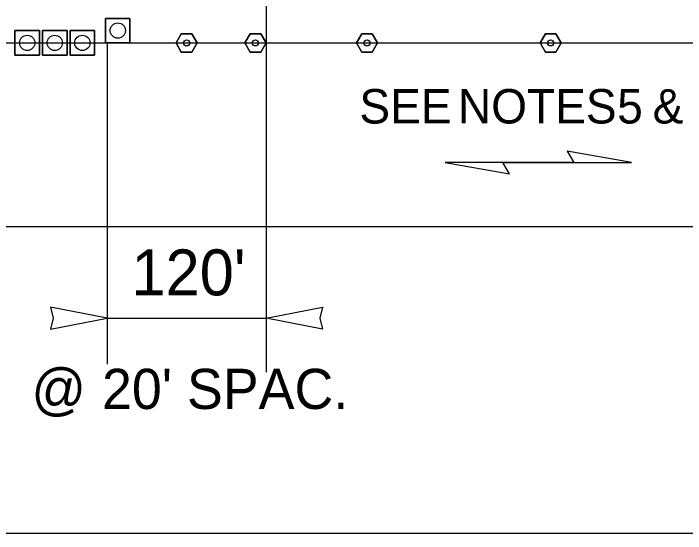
# Model space of a CAD drawing. Extents: x 99999.1 to 100095.7, y 99995 to 100010.7.
# Drawn here: x 100046.407 to 100047.578, y 100008.289 to 100009.196 of the extents above; entities that cross this region are included whole.
import ezdxf

# ---------------------------------------------------------------- set-up
doc = ezdxf.new("R2010")
doc.units = 0
for name, color, linetype in [('RD_ED_ShoulderPavedEdge', 7, 'Continuous'), ('RD_MK_LineEdgeWhite', 7, 'Continuous'), ('SH_TI_Tables', 7, 'Continuous'), ('TR_WZ_TrafficCone', 7, 'Continuous'), ('TR_WZ_TubularMarker', 7, 'Continuous'), ('TR_WZ_WorkZoneDetails', 7, 'Continuous'), ('TR_WZ_WorkZoneTextCurrent', 7, 'Continuous')]:
    doc.layers.add(name, color=color, linetype=linetype)

msp = doc.modelspace()

# ---------------------------------------------------------------- linework, layer by layer
at = {"layer": 'RD_ED_ShoulderPavedEdge'}
msp.add_line((100045.3842, 100008.8243), (100049.3016, 100008.8243), dxfattribs=at)
at = {"layer": 'RD_MK_LineEdgeWhite'}
msp.add_line((100045.3842, 100009.1443), (100049.3016, 100009.1443), dxfattribs=at)
at = {"layer": 'SH_TI_Tables'}
msp.add_lwpolyline([(100045.2702, 100010.325), (100050.7241, 100010.325), (100050.7241, 100008.2892), (100045.2702, 100008.2892)], close=True, dxfattribs=at)
at = {"layer": 'TR_WZ_TrafficCone'}
for points in [[(100046.5672, 100009.1443), (100046.6099, 100009.1443), (100046.6099, 100009.187), (100046.5672, 100009.187), (100046.5672, 100009.1443)], [(100046.5672, 100009.187), (100046.6099, 100009.187), (100046.6099, 100009.1443), (100046.5672, 100009.1443), (100046.5672, 100009.187)], [(100046.4522, 100009.1657), (100046.4095, 100009.1657), (100046.4095, 100009.123), (100046.4522, 100009.123), (100046.4522, 100009.1657)], [(100046.4522, 100009.123), (100046.4095, 100009.123), (100046.4095, 100009.1657), (100046.4522, 100009.1657), (100046.4522, 100009.123)], [(100046.5002, 100009.1657), (100046.4575, 100009.1657), (100046.4575, 100009.123), (100046.5002, 100009.123), (100046.5002, 100009.1657)], [(100046.5002, 100009.123), (100046.4575, 100009.123), (100046.4575, 100009.1657), (100046.5002, 100009.1657), (100046.5002, 100009.123)], [(100046.5482, 100009.1657), (100046.5055, 100009.1657), (100046.5055, 100009.123), (100046.5482, 100009.123), (100046.5482, 100009.1657)], [(100046.5482, 100009.123), (100046.5055, 100009.123), (100046.5055, 100009.1657), (100046.5482, 100009.1657), (100046.5482, 100009.123)]]:
    msp.add_lwpolyline(points, dxfattribs=at)
for centre in [(100046.5886, 100009.1657), (100046.4309, 100009.1443), (100046.4789, 100009.1443), (100046.5269, 100009.1443)]:
    msp.add_circle(centre, 0.0133, dxfattribs=at)
at = {"layer": 'TR_WZ_TubularMarker'}
for points in [[(100046.727, 100009.1443), (100046.7178, 100009.1603), (100046.6993, 100009.1603), (100046.6901, 100009.1443), (100046.6993, 100009.1283), (100046.7178, 100009.1283)], [(100046.847, 100009.1443), (100046.8378, 100009.1603), (100046.8193, 100009.1603), (100046.81, 100009.1443), (100046.8193, 100009.1283), (100046.8378, 100009.1283)], [(100047.0414, 100009.1443), (100047.0321, 100009.1603), (100047.0137, 100009.1603), (100047.0044, 100009.1443), (100047.0137, 100009.1283), (100047.0321, 100009.1283)], [(100047.3614, 100009.1443), (100047.3521, 100009.1603), (100047.3337, 100009.1603), (100047.3244, 100009.1443), (100047.3337, 100009.1283), (100047.3521, 100009.1283)]]:
    msp.add_lwpolyline(points, close=True, dxfattribs=at)
for points in [[(100046.7178, 100009.1283), (100046.6993, 100009.1283), (100046.6901, 100009.1443), (100046.6993, 100009.1603), (100046.7178, 100009.1603), (100046.727, 100009.1443), (100046.7178, 100009.1283)], [(100046.8378, 100009.1283), (100046.8193, 100009.1283), (100046.81, 100009.1443), (100046.8193, 100009.1603), (100046.8378, 100009.1603), (100046.847, 100009.1443), (100046.8378, 100009.1283)], [(100047.0321, 100009.1283), (100047.0137, 100009.1283), (100047.0044, 100009.1443), (100047.0137, 100009.1603), (100047.0321, 100009.1603), (100047.0414, 100009.1443), (100047.0321, 100009.1283)], [(100047.3521, 100009.1283), (100047.3337, 100009.1283), (100047.3244, 100009.1443), (100047.3337, 100009.1603), (100047.3521, 100009.1603), (100047.3614, 100009.1443), (100047.3521, 100009.1283)]]:
    msp.add_lwpolyline(points, dxfattribs=at)
for centre in [(100046.7085, 100009.1443), (100046.8285, 100009.1443), (100047.0229, 100009.1443), (100047.3429, 100009.1443)]:
    msp.add_circle(centre, 0.00533, dxfattribs=at)
at = {"layer": 'TR_WZ_WorkZoneDetails'}
for p, q in [((100046.5699, 100009.1443), (100046.5699, 100008.5843)), ((100046.8472, 100009.1443), (100046.8472, 100008.5703)), ((100047.383, 100008.9358), (100047.2595, 100008.9358)), ((100047.2595, 100008.9358), (100047.383, 100008.9358)), ((100046.5699, 100008.6643), (100046.8472, 100008.6643))]:
    msp.add_line(p, q, dxfattribs=at)
for points in [[(100046.8472, 100009.5443), (100046.8472, 100009.1443), (100047.8256, 100009.1443), (100047.8256, 100009.5443)], [(100047.4836, 100008.9358), (100047.3715, 100008.9555), (100047.383, 100008.9358)], [(100047.1589, 100008.9358), (100047.2709, 100008.916), (100047.2595, 100008.9358)], [(100046.5699, 100008.6643), (100046.4716, 100008.6836), (100046.4761, 100008.6643), (100046.4716, 100008.6451)], [(100046.8472, 100008.6643), (100046.9455, 100008.6836), (100046.9409, 100008.6643), (100046.9455, 100008.6451)]]:
    msp.add_lwpolyline(points, close=True, dxfattribs=at)

# ---------------------------------------------------------------- texts
at = {"layer": 'TR_WZ_WorkZoneTextCurrent'}
for s, p in [('SEE', (100047.0096, 100009.0038)), ('NOTES', (100047.1813, 100009.0038)), ('5', (100047.4588, 100009.0038)), ('&', (100047.5206, 100009.0038))]:
    msp.add_text(s, height=0.06, dxfattribs=at).set_placement(p)
for s, height, p in [("120'", 0.08, (100046.6124, 100008.7043)), ('@', 0.07, (100046.4383, 100008.5063)), ("20' SPAC.", 0.07, (100046.5612, 100008.5063))]:
    msp.add_text(s, height=height, rotation=360, dxfattribs=at).set_placement(p)

doc.saveas('drawing.dxf')
